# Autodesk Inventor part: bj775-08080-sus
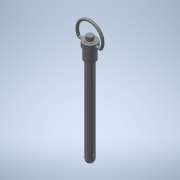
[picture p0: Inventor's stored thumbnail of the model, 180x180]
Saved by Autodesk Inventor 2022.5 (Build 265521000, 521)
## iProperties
Created: 2016-12
Part Number: bj775-08080-sus
Material: 一般
Document SubType Name: Modeling
Designer: imaocorp
Density: 1 g/cm^3
Appearance: 既定
Author: imaocorp
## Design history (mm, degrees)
node "bj775-08080-sus.x_t1"
node "bj775-08080-sus"
node "Base1"
